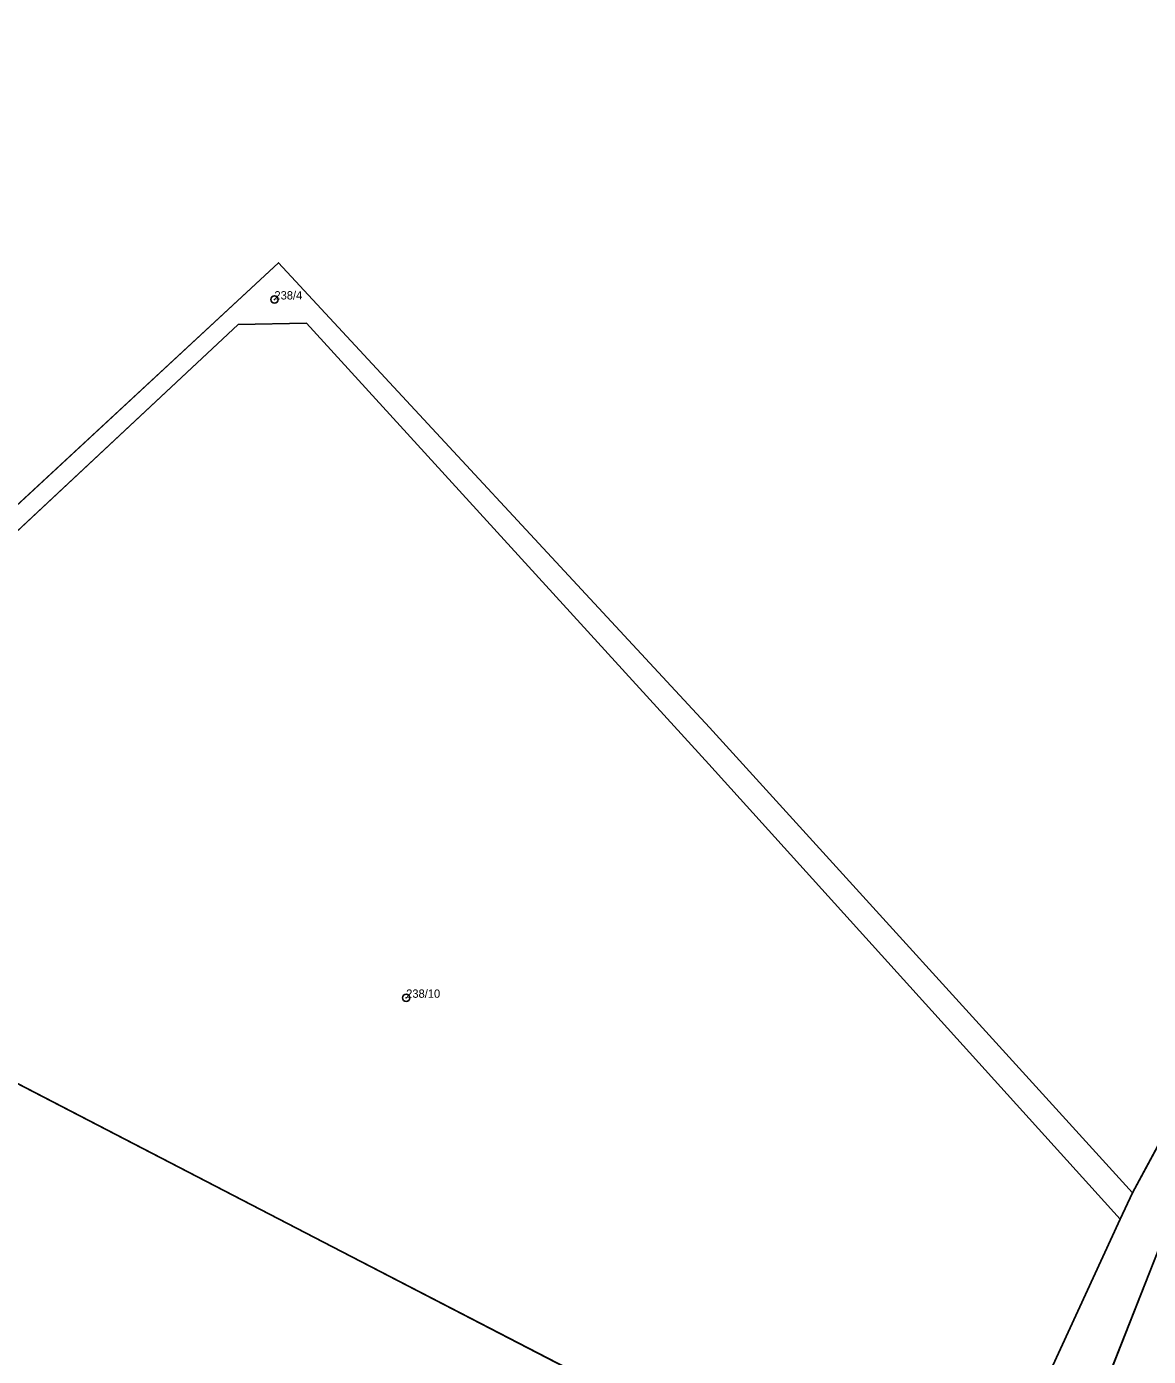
# Model space of a CAD drawing. Extents: x -652854 to -650068, y -1097661 to -1095417.
# Drawn here: x -651296.9 to -651067.4, y -1096771 to -1096498.9 of the extents above; entities that cross this region are included whole.
import ezdxf

# ---------------------------------------------------------------- set-up
doc = ezdxf.new("R2010")
doc.units = 0
for name, color, linetype in [('Definiční body parcel', 7, 'Continuous'), ('Hranice parcel', 7, 'Continuous'), ('Obvody jako plochy', 7, 'Continuous'), ('Parcelní čísla', 7, 'Continuous')]:
    doc.layers.add(name, color=color, linetype=linetype)

msp = doc.modelspace()

# ---------------------------------------------------------------- linework, layer by layer
at = {"layer": 'Definiční body parcel'}
for centre, radius in [((-651246.18, -1096554.72), 0.75), ((-651246.18, -1096554.72), 0.0327), ((-651219.23, -1096697.59), 0.75), ((-651219.23, -1096697.59), 0.0327)]:
    msp.add_circle(centre, radius, dxfattribs=at)
at = {"layer": 'Hranice parcel'}
for p, q in [((-651245.37, -1096547.21), (-651313.19, -1096610.07)), ((-651157.22, -1096642.26), (-651245.37, -1096547.21)), ((-651253.59, -1096559.84), (-651310.77, -1096613.31)), ((-651239.61, -1096559.6), (-651253.59, -1096559.84)), ((-651157.36, -1096649.81), (-651239.61, -1096559.6)), ((-651070.68, -1096737.5), (-651157.22, -1096642.26)), ((-651073.19, -1096742.86), (-651157.36, -1096649.81)), ((-651362.98, -1096681.82), (-651234.33, -1096748.53)), ((-651070.68, -1096737.5), (-651051.76, -1096702.47)), ((-651073.19, -1096742.86), (-651070.68, -1096737.5)), ((-651106.25, -1096814.79), (-651073.19, -1096742.86)), ((-651064.16, -1096746.02), (-651092.91, -1096819.19)), ((-651234.33, -1096748.53), (-651106.25, -1096814.79))]:
    msp.add_line(p, q, dxfattribs=at)
at = {"layer": 'Obvody jako plochy'}
for points in [[(-651313.19, -1096610.07), (-651245.37, -1096547.21), (-651157.22, -1096642.26), (-651070.68, -1096737.5), (-651051.76, -1096702.47), (-651039.71, -1096659.27), (-651020.73, -1096600.77), (-651004.79, -1096566.57), (-651003.94, -1096568.48), (-651000.71, -1096567.63), (-650997.98, -1096467.04)], [(-650997.98, -1096467.04), (-651000.71, -1096567.63), (-651003.94, -1096568.48), (-651004.79, -1096566.57), (-651020.73, -1096600.77), (-651039.71, -1096659.27), (-651051.76, -1096702.47), (-651070.68, -1096737.5), (-651073.19, -1096742.86), (-651106.25, -1096814.79), (-651107.57, -1096817.82), (-651148.03, -1096849.31), (-651191.03, -1096866.63), (-651219.12, -1096888.73), (-651229.34, -1096915.13), (-651247.74, -1096949.65), (-651252.18, -1096966.63), (-651244.09, -1096981.31), (-651242.12, -1096996.77), (-651260.99, -1097064.52), (-651285.08, -1097185.42)], [(-651265.36, -1097103.05), (-651257.34, -1097063.72), (-651247.51, -1097028.99), (-651245.41, -1097021.38), (-651239.04, -1096997.1), (-651238.32, -1096950.99), (-651221.71, -1096910.45), (-651212.01, -1096895.47), (-651185.65, -1096873.07), (-651139.25, -1096852.14), (-651118.15, -1096866.81), (-651116.22, -1096863.89), (-651118.03, -1096862.54), (-651092.91, -1096819.19), (-651064.16, -1096746.02), (-651057.86, -1096732.59), (-651054.18, -1096725.78), (-651044.25, -1096705.46), (-651031.97, -1096667.36), (-651013.64, -1096606.83), (-651005.54, -1096598.62), (-650996.98, -1096566.77), (-650986.75, -1096469.56)]]:
    msp.add_lwpolyline(points, dxfattribs=at)
for points in [[(-651435.11, -1096707.84), (-651518.41, -1096775.28), (-651516.85, -1096778.46), (-651432.26, -1096709), (-651310.77, -1096613.31), (-651253.59, -1096559.84), (-651239.61, -1096559.6), (-651157.36, -1096649.81), (-651073.19, -1096742.86), (-651070.68, -1096737.5), (-651157.22, -1096642.26), (-651245.37, -1096547.21), (-651313.19, -1096610.07)], [(-651377.52, -1096988.66), (-651378.36, -1096871.23), (-651378.55, -1096753.88), (-651366.75, -1096677.34), (-651362.98, -1096681.82), (-651234.33, -1096748.53), (-651106.25, -1096814.79), (-651073.19, -1096742.86), (-651157.36, -1096649.81), (-651239.61, -1096559.6), (-651253.59, -1096559.84), (-651310.77, -1096613.31), (-651432.26, -1096709), (-651516.85, -1096778.46), (-651480.45, -1096885.67), (-651444.66, -1096993.23)], [(-651294.29, -1097048.39), (-651260.99, -1097064.52), (-651242.12, -1096996.77), (-651244.09, -1096981.31), (-651252.18, -1096966.63), (-651247.74, -1096949.65), (-651229.34, -1096915.13), (-651219.12, -1096888.73), (-651191.03, -1096866.63), (-651148.03, -1096849.31), (-651107.57, -1096817.82), (-651106.25, -1096814.79), (-651234.33, -1096748.53), (-651362.98, -1096681.82), (-651366.75, -1096677.34), (-651378.55, -1096753.88), (-651378.36, -1096871.23), (-651377.52, -1096988.66), (-651345.79, -1097007.69), (-651288.56, -1097037.08)], [(-650991.73, -1096930.73), (-650977.36, -1096938.43), (-650951.86, -1096894.94), (-650929.11, -1096871.18), (-650990.9, -1096823.82), (-651054.18, -1096725.78), (-651057.86, -1096732.59), (-651064.16, -1096746.02), (-651092.91, -1096819.19), (-651118.03, -1096862.54), (-651116.22, -1096863.89), (-651076.39, -1096886.18), (-651073.22, -1096897.77), (-650993.08, -1096933.27)]]:
    msp.add_lwpolyline(points, close=True, dxfattribs=at)

# ---------------------------------------------------------------- texts
at = {"layer": 'Parcelní čísla'}
for s, p in [('238/4', (-651246.18, -1096554.72)), ('238/10', (-651219.23, -1096697.59))]:
    msp.add_text(s, height=1.7, dxfattribs=at).set_placement(p)

doc.saveas('drawing.dxf')
